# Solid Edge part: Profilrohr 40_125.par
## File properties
Username: ahadarics
Dokumentum tartalom típus: 0
Author: ahadarics
Last saved by: ahadarics
Revision: 82
Sűrűség: 0,000 kg/m^3
Pontosság: 0,990
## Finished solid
Body 1: solid body, 175 faces, 519 edges, 346 vertices.
  Faces by surface: cylinder 107, plane 68
  Edges by curve: line 305, circle 214
Bounding box of the edges (mm): 51.354 x 51.354 x 168.000, from (-25.6768, -25.6768, -59) to (25.6768, 25.6768, 109).
Cylindrical faces by radius (mm): R0.1 x16, R0.2 x30, R0.5 x28, R1 x8, R2.7 x8, R3.5 x4, R5 x4, R20 x1, R22 x8
Planar faces by outward normal: +x 6, +y 6, +z 1, -x 4, -y 4, -z 1, oblique 46
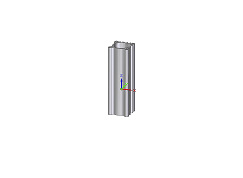
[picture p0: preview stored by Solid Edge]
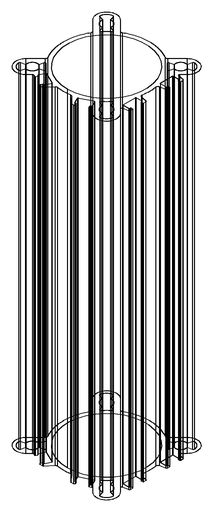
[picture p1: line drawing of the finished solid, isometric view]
